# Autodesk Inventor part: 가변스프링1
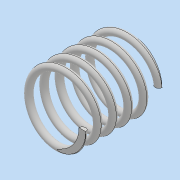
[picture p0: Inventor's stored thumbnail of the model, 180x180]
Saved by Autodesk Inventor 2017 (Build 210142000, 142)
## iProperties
Part Number: 가변스프링1
Material: 일반
Document SubType Name: Modeling
Designer: MRC
Density: 1 g/cm^3
Appearance: 기본값
Author: MRC
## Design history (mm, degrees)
sketch "스케치1"
  geometry: L1 (0, 0)-(0, 22.5); L2 (0, 22.5)-(9, 22.5); L3 (0, 0)-(9, 0); C1 r 1 at (9, 0)
  constraints: 6 end point, 2 horizontal, 1 centre point, 1 coincident, 1 vertical
  dimensions: "d0" = 22.5 distance of L1.start L1.end (derived); "d1" = 9 distance of L1.end L2.end; "d2" = 9 distance of L1.start L3.end; "d3" = 2 diameter of C1
feature "코일1" sketch "스케치1" pitch "d4" = 10; turns "d6" = 5; dims "d5" = 22.5 (= d0), "d7" = 0, angle "d8" = 90 deg, angle "d9" = 90 deg, "d10" = 0, "d11" = 0
sketch "스케치2"
  geometry: L1 (22.5, 21.748)-(0, 21.748); L2 (0, 21.748)-(0, -21.748); L3 (0, -21.748)-(22.5, -21.748); L4 (22.5, -21.748)-(22.5, 21.748); 2 further points
  constraints: 8 end point, 2 midpoint, 2 parallel, 1 coincident, 1 horizontal, 1 perpendicular
  dimensions: "d12" = 22.5 distance of L2.end L3.end (= d0); "d13" = 43.49633 distance of L3.end L1.start
extrude "돌출1" sketch "스케치2" stored distance "d14" = 0; taper "d15" = 0 deg
node "솔리드1"
